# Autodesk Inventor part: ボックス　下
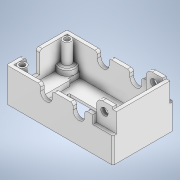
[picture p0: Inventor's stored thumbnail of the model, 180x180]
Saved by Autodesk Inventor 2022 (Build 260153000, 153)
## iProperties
Created: 2024-12
Part Number: ボックス　下
Material: LCP プラスチック
Document SubType Name: Modeling
Designer: jsat7
Density: 1.626 g/cm^3
Appearance: 滑らか - 白
Author: jsat7
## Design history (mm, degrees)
sketch "スケッチ1"
  geometry: L1 (20.943, -13.706)-(-23.057, -13.706); L2 (-23.057, -13.706)-(-23.057, 11.294); L3 (-23.057, 11.294)-(20.943, 11.294); L4 (20.943, 11.294)-(20.943, -13.706); 1 further point
  constraints: 8 end point, 2 parallel, 1 horizontal, 1 perpendicular
  dimensions: "d0" = 25 distance of L3.end L1.start; "d1" = 44 distance of L1.start L1.end
extrude "押し出し1" new body sketch "スケッチ1" distance "d2" = 1; taper "d3" = 0 deg
sketch "スケッチ2"
  geometry: L1 (-19.443, 12.206)-(21.557, 12.206); L2 (21.557, 12.206)-(21.557, -9.794); L3 (21.557, -9.794)-(-19.443, -9.794); L4 (-19.443, -9.794)-(-19.443, 12.206); L5 (-20.943, 13.706)-(-20.943, -11.294) reference; L6 (23.057, 13.706)-(-20.943, 13.706) reference; L7 (23.057, -11.294)-(23.057, 13.706) reference; L8 (-20.943, -11.294)-(23.057, -11.294) reference; L9 (-20.943, 13.706)-(23.057, 13.706); L10 (23.057, 13.706)-(23.057, -11.294); L11 (23.057, -11.294)-(-20.943, -11.294); L12 (-20.943, -11.294)-(-20.943, 13.706); 1 further point
  constraints: 16 end point, 4 parallel, 2 horizontal, 2 perpendicular
  dimensions: "d110" = 1.5 distance between parallel lines of L8 L3
extrude "押し出し2" join sketch "スケッチ2" distance "d8" = 13; taper "d9" = 0 deg
sketch "スケッチ3"
  geometry: L1 (-19.443, 12.206)-(21.557, 12.206) reference; L2 (23.057, -11.294)-(23.057, 13.706) reference; L3 (21.557, 12.206)-(23.057, 12.206); L4 (23.057, 12.206)-(23.057, -9.794); L5 (23.057, -9.794)-(21.557, -9.794); L6 (21.557, -9.794)-(21.557, 12.206); 2 further points
  constraints: 8 end point, 2 parallel, 1 horizontal, 1 perpendicular, 1 point on line
  dimensions: "d10" = 22 distance between parallel lines of L5 L3
extrude "押し出し3" join sketch "スケッチ3" distance "d11" = 4.5; taper "d12" = 0 deg
sketch "スケッチ4"
  geometry: L1 (21.557, -9.794)-(-19.443, -9.794) reference; L2 (23.057, -11.294)-(14.757, -11.294); L3 (14.757, -11.294)-(14.757, -9.794); L4 (14.757, -9.794)-(23.057, -9.794); L5 (23.057, -9.794)-(23.057, -11.294); L6 (23.057, 12.206)-(21.557, 12.206) reference; L7 (23.057, 13.706)-(-20.943, 13.706) reference; L8 (23.057, 12.206)-(14.757, 12.206); L9 (14.757, 12.206)-(14.757, 13.706); L10 (14.757, 13.706)-(23.057, 13.706); L11 (23.057, 13.706)-(23.057, 12.206); 4 further points
  constraints: 16 end point, 4 parallel, 2 horizontal, 2 perpendicular, 2 point on line
  dimensions: "d13" = 8.3 distance between parallel lines of L11 L9; "d14" = 8.3 distance between parallel lines of L5 L3
extrude "押し出し4" cut sketch "スケッチ4" distance "d15" = 3.5; taper "d16" = 0 deg
sketch "スケッチ5"
  geometry: L1 (21.557, -9.794)-(21.557, 12.206) reference; L2 (21.557, -9.794)-(14.757, -9.794); L3 (14.757, -9.794)-(14.757, -8.294); L4 (14.757, -8.294)-(21.557, -8.294); L5 (21.557, -8.294)-(21.557, -9.794); L6 (21.557, 12.206)-(14.757, 12.206); L7 (14.757, 12.206)-(14.757, 10.706); L8 (14.757, 10.706)-(21.557, 10.706); L9 (21.557, 10.706)-(21.557, 12.206); 3 further points
  constraints: 16 end point, 4 parallel, 2 horizontal, 2 perpendicular, 1 point on line
  dimensions: "d17" = 6.8 distance between parallel lines of L7 L1; "d18" = 1.5 distance between parallel lines of L4 L2; "d19" = 1.5 distance between parallel lines of L8 L6
extrude "押し出し5" join sketch "スケッチ5" distance "d20" = 18.5; taper "d21" = 0 deg
sketch "スケッチ6"
  geometry: L1 (0, 8)-(0, 0) reference; L2 (-8.3, 9)-(-1.5, 9) reference; C1 r 1.5 at (-5, 5.5); 1 further point
  constraints: 1 centre point
  dimensions: "d22" = 3 diameter of C1; "d23" = 5 distance from line of L1 C1.centre; "d24" = 3.5 distance from line of C1.centre L2
extrude "押し出し6" cut sketch "スケッチ6" distance "d25" = 25; taper "d26" = 0 deg
sketch "スケッチ8"
  geometry: L1 (0, 14)-(35.7, 14) reference; L2 (0, 0)-(0, 14) reference; L3 (35.7, 14)-(1.5, 14) reference; C1 r 2.45 at (16.45, 11.55); C2 r 2.45 at (29.95, 11.55); 2 further points
  constraints: 2 centre point, 1 tangent
  dimensions: "d37" = 4.9 diameter of C1; "d38" = 2.45 distance from line of L1 C1.centre; "d39" = 16.45 distance from line of L2 C1.centre; "d40" = 13.5 distance of C2.centre C1.centre; "d41" = 4.9 diameter of C2
extrude "押し出し8" cut sketch "スケッチ8" distance "d42" = 28; taper "d43" = 0 deg
sketch "スケッチ9"
  geometry: L1 (14, 15.507)-(18.9, 15.507); L2 (18.9, 15.507)-(18.9, 11.55); L3 (18.9, 11.55)-(14, 11.55); L4 (14, 11.55)-(14, 15.507); A1 r 2.45 centre (16.45, 11.55) between (18.9, 11.55) and (16.45, 14) reference; 2 further points
  constraints: 8 end point, 2 parallel, 1 horizontal, 1 perpendicular, 1 point on circle
extrude "押し出し9" cut sketch "スケッチ9" distance "d44" = 28; taper "d45" = 0 deg
sketch "スケッチ10"
  geometry: L1 (27.5, 11.55)-(32.4, 11.55); L2 (32.4, 11.55)-(32.4, 16.799); L3 (32.4, 16.799)-(27.5, 16.799); L4 (27.5, 16.799)-(27.5, 11.55); A1 r 2.45 centre (29.95, 11.55) between (27.5, 11.55) and (29.95, 14) reference; 2 further points
  constraints: 8 end point, 2 parallel, 1 horizontal, 1 perpendicular, 1 point on circle
extrude "押し出し10" cut sketch "スケッチ10" distance "d46" = 28; taper "d47" = 0 deg
fillet "フィレット1" dims "d48" = 1
fillet "フィレット2" dims "d49" = 1
fillet "フィレット3" dims "d50" = 2.5
fillet "フィレット4" dims "d51" = 2.5
sketch "スケッチ12"
  geometry: L1 (23.5, 14)-(1.5, 14) reference; L2 (12.8, 14)-(18.3, 14); L3 (18.3, 14)-(18.3, 5); L4 (18.3, 5)-(12.8, 5); L5 (12.8, 5)-(12.8, 14); L6 (0, 0)-(25, 0) reference; L7 (25, 0)-(25, 14) reference; L8 (0, 0)-(0, 14) reference; 4 further points
  constraints: 8 end point, 2 parallel, 1 horizontal, 1 perpendicular, 1 point on line
  dimensions: "d52" = 5 distance between parallel lines of L6 L4; "d53" = 6.7 distance between parallel lines of L7 L3; "d54" = 12.8 distance between parallel lines of L8 L5
extrude "押し出し11" cut sketch "スケッチ12" distance "d55" = 1.5; taper "d56" = 0 deg
fillet "フィレット5" dims "d57" = 1
fillet "フィレット6" dims "d58" = 1
chamfer "面取り1" distance "d59" = 0.5; stored, may be unused: second distance "d60" = 2, angle "d61" = 45 deg
sketch "スケッチ13"
  geometry: L1 (-19.443, 12.206)-(-19.443, -9.794) reference; L2 (-19.443, -9.794)-(14.757, -9.794) reference; L3 (-19.443, 12.206)-(-14.143, 12.206); L4 (-14.143, 12.206)-(-14.143, -9.794); L5 (-14.143, -9.794)-(-19.443, -9.794); L6 (-19.443, -9.794)-(-19.443, 12.206); L7 (-14.143, 7.456)-(-13.143, 7.456); L8 (-13.143, 7.456)-(-13.143, -5.044); L9 (-13.143, -5.044)-(-14.143, -5.044); L10 (-14.143, -5.044)-(-14.143, 7.456); 2 further points
  constraints: 16 end point, 4 parallel, 2 horizontal, 2 perpendicular, 2 point on line
  dimensions: "d62" = 5.3 distance between parallel lines of L4 L1; "d63" = 1 distance between parallel lines of L8 L4; "d64" = 12.5 distance between parallel lines of L9 L7; "d65" = 4.75 distance between parallel lines of L7 L3
extrude "押し出し12" join sketch "スケッチ13" distance "d66" = 2.2; taper "d67" = 0 deg
sketch "スケッチ14"
  geometry: L1 (-14.143, 7.456)-(-14.143, 12.206) reference; L2 (-7.943, 13.706)-(-20.443, 13.706) reference; L3 (-20.443, -11.294)-(-7.943, -11.294) reference; L4 (-20.943, -5.594)-(-20.943, -10.794) reference; C1 r 3.4 at (-17.543, 10.306); C2 r 3.4 at (-17.543, -7.894); 1 further point
  constraints: 2 centre point
  dimensions: "d68" = 3.4 distance from line of L1 C1.centre; "d69" = 3.4 distance from line of L2 C1.centre; "d70" = 6.8 diameter of C1; "d71" = 3.4 distance from line of L3 C2.centre; "d72" = 3.4 distance from line of L4 C2.centre; "d73" = 6.8 diameter of C2
extrude "押し出し13" join sketch "スケッチ14" distance "d74" = 2.5; taper "d75" = 0 deg
sketch "スケッチ15"
  geometry: L1 (-20.943, 13.206)-(-20.943, 1.906) reference; L2 (-7.943, 13.706)-(-20.443, 13.706) reference; L3 (-20.943, -5.594)-(-20.943, -10.794) reference; L4 (-20.443, -11.294)-(-7.943, -11.294) reference; C1 r 1.75 at (-17.693, 10.456); C2 r 1.75 at (-17.693, -8.044); C3 r 1.1 at (-17.693, -8.044); C4 r 1.1 at (-17.693, 10.456); C5 r 1.1 at (-17.693, 10.456); 1 further point
  constraints: 5 centre point, 3 coincident, 1 concentric
  dimensions: "d76" = 3.25 distance from line of L1 C1.centre; "d77" = 3.25 distance from line of L2 C1.centre; "d78" = 3.5 diameter of C1; "d79" = 3.25 distance from line of L3 C2.centre; "d80" = 3.25 distance from line of L4 C2.centre; "d81" = 3.5 diameter of C2; "d82" = 2.2 diameter of C3; "d83" = 2.2 diameter of C4
extrude "押し出し14" join sketch "スケッチ15" distance "d84" = 8.3; taper "d85" = 0 deg
fillet "フィレット7" dims "d86" = 0.5
fillet "フィレット8" dims "d87" = 0.5
fillet "フィレット9" dims "d88" = 0.5
fillet "フィレット10" dims "d89" = 0.5
sketch "スケッチ16"
  geometry: C1 r 1.1 at (0, 0); 1 further point
  constraints: 1 centre point
extrude "押し出し15" cut sketch "スケッチ16" distance "d90" = 10; taper "d91" = 0 deg
sketch "スケッチ17"
  geometry: C1 r 1.1 at (0, 0); A1 r 1.75 centre (0, 0) between (0, -1.75) and (-1.75, 0) reference; 1 further point
  constraints: 1 centre point, 1 coincident
extrude "押し出し16" cut sketch "スケッチ17" distance "d92" = 10; taper "d93" = 0 deg
sketch "スケッチ18"
  geometry: L1 (2.157, 7.106)-(15.857, 7.106); L2 (15.857, 7.106)-(15.857, -4.594); L3 (15.857, -4.594)-(2.157, -4.594); L4 (2.157, -4.594)-(2.157, 7.106); L5 (6.557, 13.706)-(11.457, 13.706) reference; L6 (23.057, -9.794)-(23.057, 12.206) reference; L7 (2.157, 4.406)-(-10.743, 4.406); L8 (-10.743, 4.406)-(-10.743, -7.794); L9 (-10.743, -7.794)-(2.157, -7.794); L10 (2.157, -7.794)-(2.157, 4.406); L11 (-2.043, -11.294)-(-6.943, -11.294) reference; L12 (-20.943, -4.594)-(-20.943, 0.906) reference; L13 (-6.943, 13.706)-(-2.043, 13.706) reference; 2 further points
  constraints: 16 end point, 4 parallel, 2 horizontal, 2 perpendicular, 1 point on line
  dimensions: "d94" = 6.6 distance between parallel lines of L5 L1; "d95" = 7.2 distance between parallel lines of L6 L2; "d96" = 13.7 distance between parallel lines of L2 L4; "d97" = 11.7 distance between parallel lines of L3 L1; "d98" = 3.5 distance between parallel lines of L11 L9; "d99" = 10.2 distance between parallel lines of L12 L8; "d100" = 9.3 distance between parallel lines of L7 L13
extrude "押し出し17" cut sketch "スケッチ18" distance "d101" = 1.5; taper "d102" = 0 deg
fillet "フィレット11" dims "d103" = 0.5
fillet "フィレット12" dims "d104" = 0.5
fillet "フィレット13" dims "d105" = 0.5
fillet "フィレット14" dims "d106" = 0.5
fillet "フィレット15" dims "d107" = 0.5
fillet "フィレット16" dims "d108" = 0.5
fillet "フィレット17" dims "d109" = 0.5
node "ソリッド1"
